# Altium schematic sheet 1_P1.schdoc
size 431 x 309 mm; Symbol: Sheet-Symbol_A4; Device: Sheet-Symbol_A4; @Page Name: P1; @Create Date: 2023-06-03; @Page Count: 1; @Page No: 1; @Project Name: ESP32-S3最小系统板; @Schematic Name: Schematic1; @Update Date: 2023-06-13; Company: 嘉立创EDA; Page Size: A4; Version: V1.0
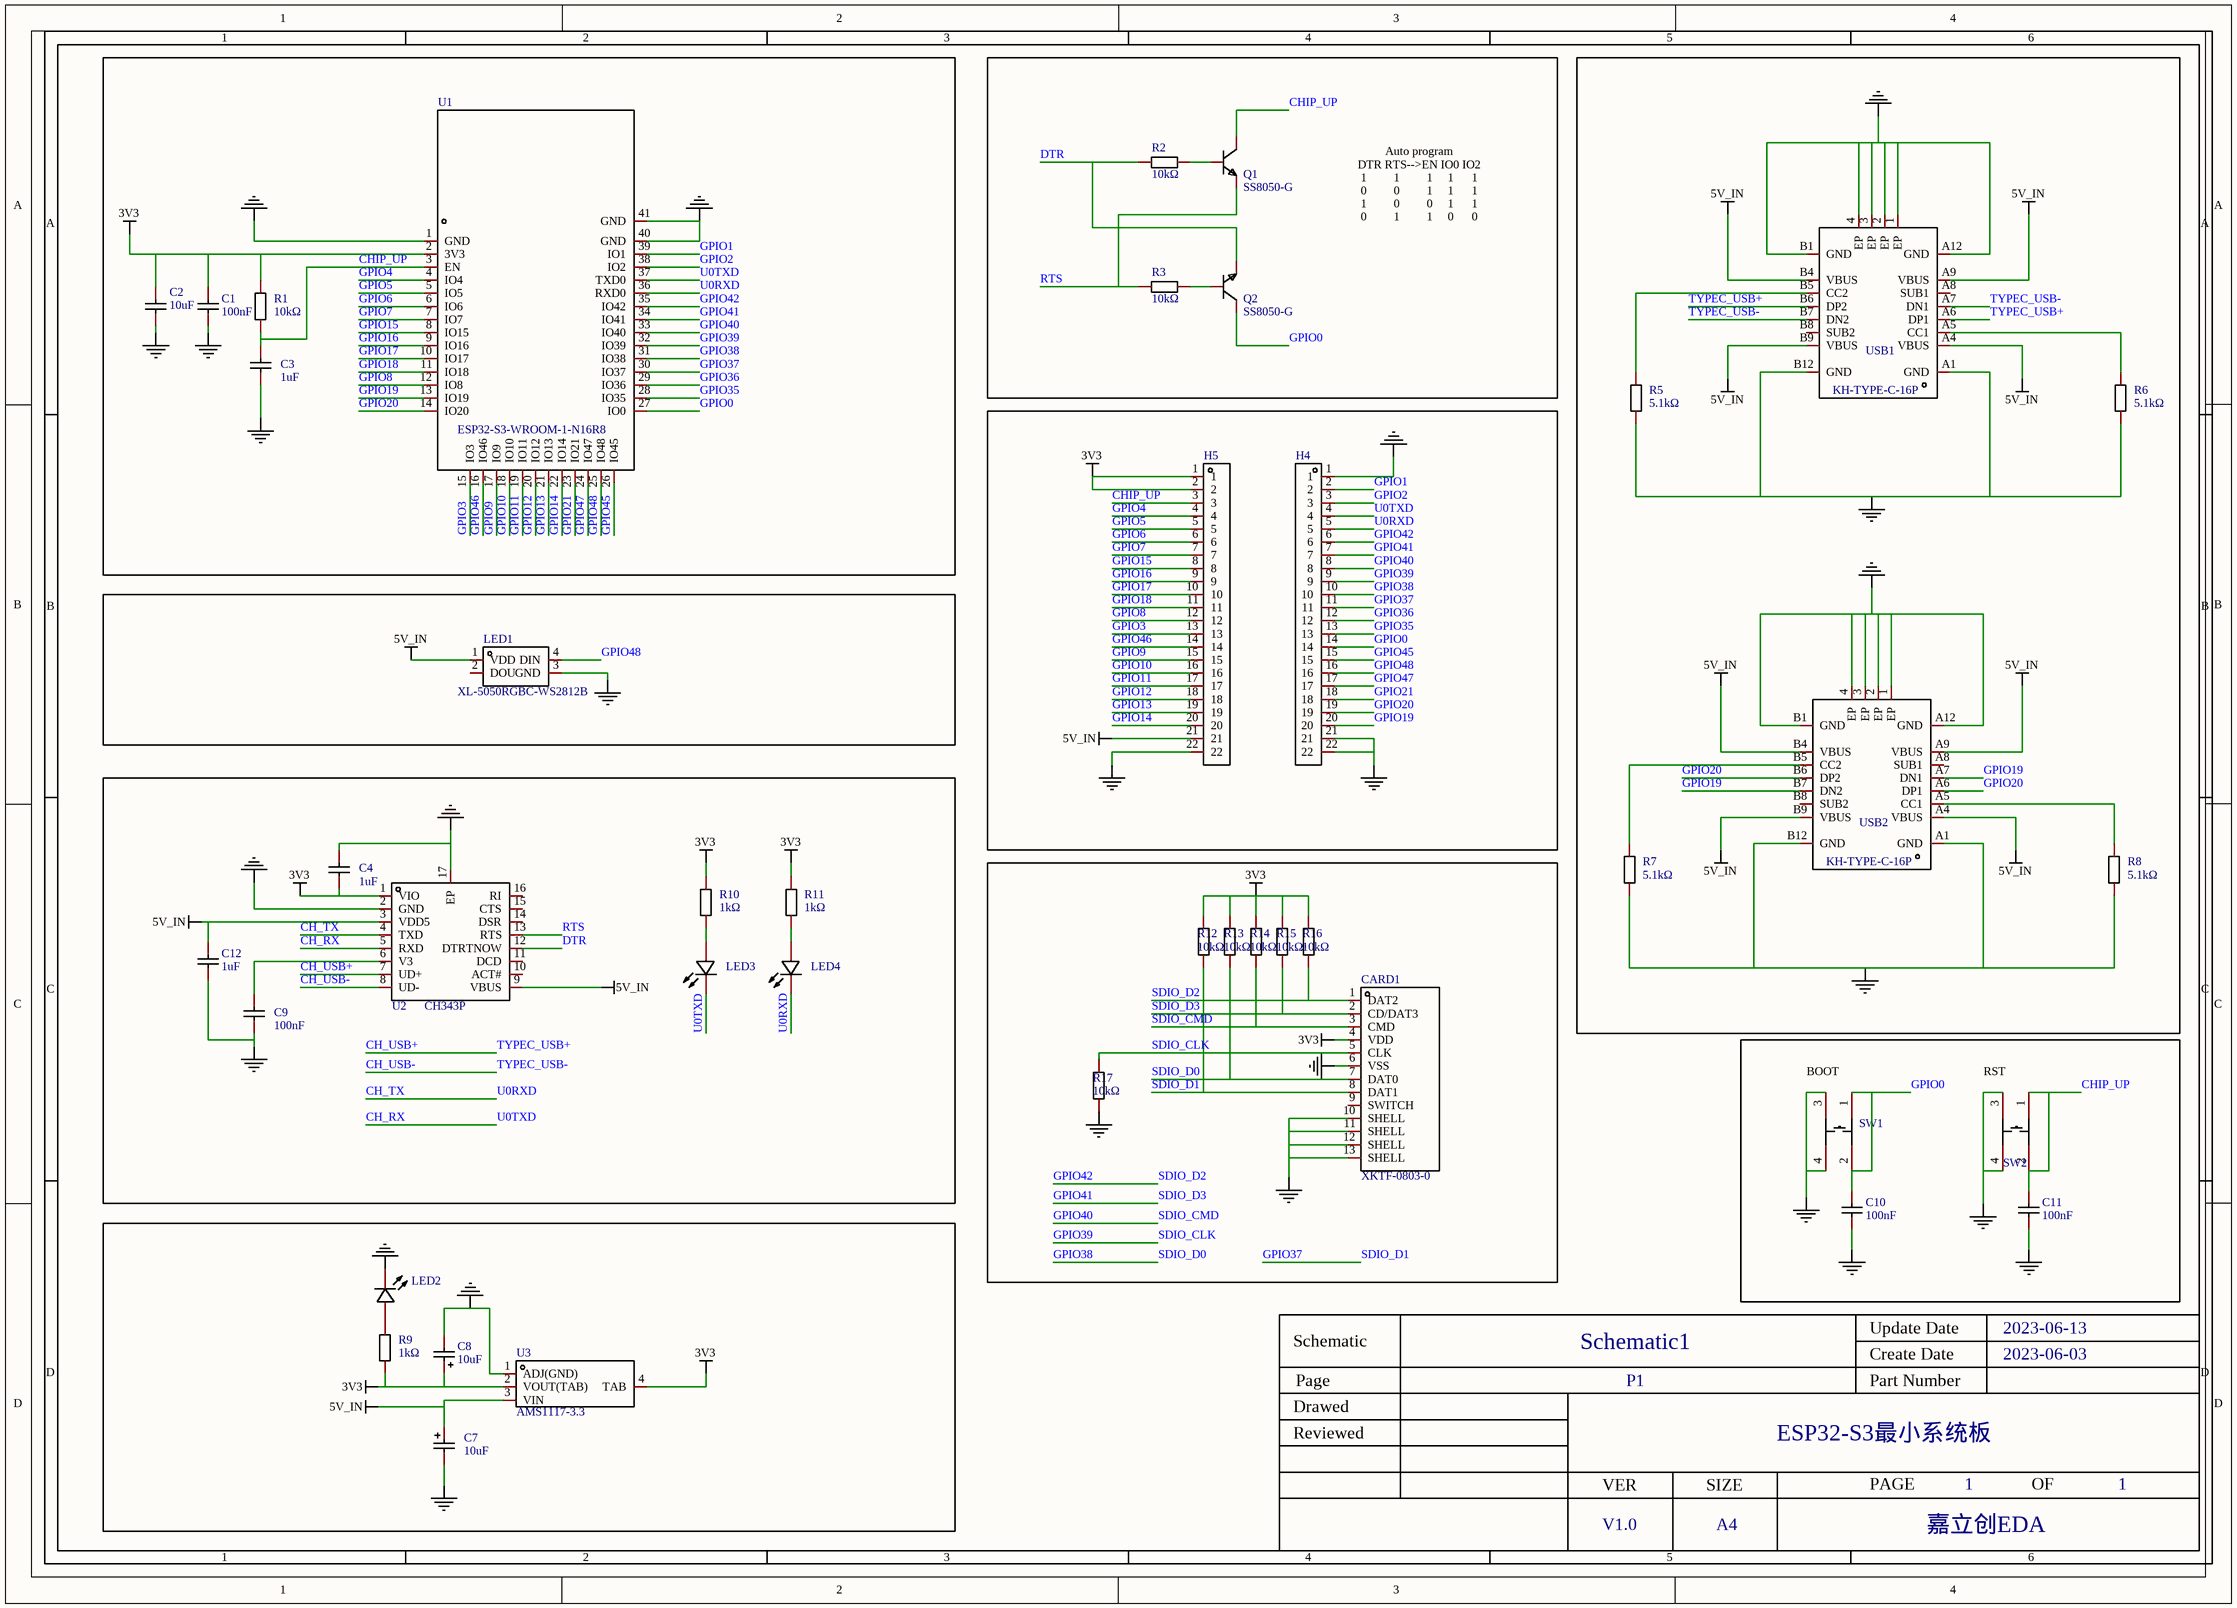
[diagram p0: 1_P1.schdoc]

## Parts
C1  100nF  [C0805]
C2  10uF  [C0805]
C3  1uF  [C0805]
C4  1uF  [C0805]
C7  10uF  [CAP-SMD_L3.2-W1.6-RD-C7171]
C8  10uF  [CAP-SMD_L3.2-W1.6-RD-C7171]
C9  100nF  [C0805]
C10  100nF  [C0805]
C11  100nF  [C0805]
C12  1uF  [C0805]
CARD1  XKTF-0803-0  [TF-SMD_XKTF-0803-0]
H4  X6511WV-22H-C30D60  [HDR-TH_22P-P2.54-V-M]  (value not drawn)
H5  X6511WV-22H-C30D60  [HDR-TH_22P-P2.54-V-M]  (value not drawn)
LED1  XL-5050RGBC-WS2812B  [LED-SMD_4P-L5.0-W5.0-BL_XL-5050RGBC]
LED2  NCD0805R1  [LED0805-RD_RED]  (value not drawn)
LED3  SZYY0805B  [LED0805-R-RD_BLUE]  (value not drawn)
LED4  SZYY0805B  [LED0805-R-RD_BLUE]  (value not drawn)
Q1  SS8050-G  [SOT-23-3_L2.9-W1.6-P1.90-LS2.8-BR]
Q2  SS8050-G  [SOT-23-3_L2.9-W1.6-P1.90-LS2.8-BR]
R1  10kΩ  [R0805]
R2  10kΩ  [R0805]
R3  10kΩ  [R0805]
R5  5.1kΩ  [R0805]
R6  5.1kΩ  [R0805]
R7  5.1kΩ  [R0805]
R8  5.1kΩ  [R0805]
R9  1kΩ  [R0805]
R10  1kΩ  [R0805]
R11  1kΩ  [R0805]
R12  10kΩ  [R0805]
R13  10kΩ  [R0805]
R14  10kΩ  [R0805]
R15  10kΩ  [R0805]
R16  10kΩ  [R0805]
R17  10kΩ  [R0805]
SW1  SKRPACE010  [KEY-SMD_4P-L4.2-W3.2-P2.20-LS4.6]  (value not drawn)
SW2  SKRPACE010  [KEY-SMD_4P-L4.2-W3.2-P2.20-LS4.6]  (value not drawn)
U1  ESP32-S3-WROOM-1-N16R8  [WIRELM-SMD_ESP32-S3-WROOM-1]
U2  CH343P  [TQFN-16_L3.0-W3.0-P0.50-BL-EP1.7]
U3  AMS1117-3.3  [SOT-223-4_L6.5-W3.5-P2.30-LS7.0-BR]
USB1  KH-TYPE-C-16P  [USB-C-SMD_KH-TYPE-C-16P]
USB2  KH-TYPE-C-16P  [USB-C-SMD_KH-TYPE-C-16P]

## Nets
3V3: C1.2 C2.2 C4.1 C8.1 CARD1.4(VDD) H5.1 H5.2 R1.2 R9.1 R10.2 R11.2 R12.2 R13.2 R14.2 R15.2 R16.2 U1.2(3V3) U2.1(VIO) U3.2(VOUT(TAB)) U3.4(TAB)
5V_IN: C7.1 C12.2 H5.21 LED1.1(VDD) U2.3(VDD5) U2.9(VBUS) U3.3(VIN) USB1.A4(VBUS) USB1.A9(VBUS) USB1.B4(VBUS) USB1.B9(VBUS) USB2.A4(VBUS) USB2.A9(VBUS) USB2.B4(VBUS) USB2.B9(VBUS)
NetC1_1: C1.1 C2.1 C3.1 C4.2 C7.2 C8.2 C9.1 C10.1 C11.1 C12.1 CARD1.6(VSS) CARD1.10(SHELL) CARD1.11(SHELL) CARD1.12(SHELL) CARD1.13(SHELL) H4.1 H4.21 H4.22 H5.22 LED1.3(GND) LED2.1(-) R5.1 R6.1 R7.1 R8.1 R17.1 SW1.3 SW1.4 SW2.3 SW2.4 U1.1(GND) U1.40(GND) U1.41(GND) U2.2(GND) U2.17(EP) U3.1(ADJ(GND)) USB1.1(EP) USB1.2(EP) USB1.3(EP) USB1.4(EP) USB1.A1(GND) USB1.A12(GND) USB1.B1(GND) USB1.B12(GND) USB2.1(EP) USB2.2(EP) USB2.3(EP) USB2.4(EP) USB2.A1(GND) USB2.A12(GND) USB2.B1(GND) USB2.B12(GND)
CH_RX: H4.4 LED3.2(-) U1.37(TXD0) U2.5(RXD)  [also labelled U0TXD]
CH_TX: H4.5 LED4.2(-) U1.36(RXD0) U2.4(TXD)  [also labelled U0RXD]
CH_USB+: U2.7(UD+) USB1.A6(DP1) USB1.B6(DP2)  [also labelled TYPEC_USB+]
CH_USB-: U2.8(UD-) USB1.A7(DN1) USB1.B7(DN2)  [also labelled TYPEC_USB-]
CHIP_UP: C3.2 C11.2 H5.3 Q1.3(C) R1.1 SW2.1 SW2.2 U1.3(EN)
DTR: Q2.2(E) R2.2 U2.12(DTRTNOW)
GPIO0: C10.2 H4.14 Q2.3(C) SW1.1 SW1.2 U1.27(IO0)
GPIO1: H4.2 U1.39(IO1)
GPIO2: H4.3 U1.38(IO2)
GPIO3: H5.13 U1.15(IO3)
GPIO4: H5.4 U1.4(IO4)
GPIO5: H5.5 U1.5(IO5)
GPIO6: H5.6 U1.6(IO6)
GPIO7: H5.7 U1.7(IO7)
GPIO8: H5.12 U1.12(IO8)
GPIO9: H5.15 U1.17(IO9)
GPIO10: H5.16 U1.18(IO10)
GPIO11: H5.17 U1.19(IO11)
GPIO12: H5.18 U1.20(IO12)
GPIO13: H5.19 U1.21(IO13)
GPIO14: H5.20 U1.22(IO14)
GPIO15: H5.8 U1.8(IO15)
GPIO16: H5.9 U1.9(IO16)
GPIO17: H5.10 U1.10(IO17)
GPIO18: H5.11 U1.11(IO18)
GPIO19: H4.20 U1.13(IO19) USB2.A7(DN1) USB2.B7(DN2)
GPIO20: H4.19 U1.14(IO20) USB2.A6(DP1) USB2.B6(DP2)
GPIO21: H4.18 U1.23(IO21)
GPIO35: H4.13 U1.28(IO35)
GPIO36: H4.12 U1.29(IO36)
GPIO37: CARD1.8(DAT1) H4.11 R12.1 U1.30(IO37)  [also labelled SDIO_D1]
GPIO38: CARD1.7(DAT0) H4.10 R13.1 U1.31(IO38)  [also labelled SDIO_D0]
GPIO39: CARD1.5(CLK) H4.9 R17.2 U1.32(IO39)  [also labelled SDIO_CLK]
GPIO40: CARD1.3(CMD) H4.8 R14.1 U1.33(IO40)  [also labelled SDIO_CMD]
GPIO41: CARD1.2(CD/DAT3) H4.7 R15.1 U1.34(IO41)  [also labelled SDIO_D3]
GPIO42: CARD1.1(DAT2) H4.6 R16.1 U1.35(IO42)  [also labelled SDIO_D2]
GPIO45: H4.15 U1.26(IO45)
GPIO46: H5.14 U1.16(IO46)
GPIO47: H4.17 U1.24(IO47)
GPIO48: H4.16 LED1.4(DIN) U1.25(IO48)
RTS: Q1.2(E) R3.2 U2.13(RTS)
NetC9_2: C9.2 U2.6(V3)
NetLED2_2: LED2.2(+) R9.2
NetLED3_1: LED3.1(+) R10.1
NetLED4_1: LED4.1(+) R11.1
NetQ1_1: Q1.1(B) R2.1
NetQ2_1: Q2.1(B) R3.1
NetR5_2: R5.2 USB1.B5(CC2)
NetR6_2: R6.2 USB1.A5(CC1)
NetR7_2: R7.2 USB2.B5(CC2)
NetR8_2: R8.2 USB2.A5(CC1)

Not connected (* = marked no-connect by the designer): CARD1 9(SWITCH); LED1 2(DOU); U2 10(ACT#) 11(DCD) 14(DSR) 15(CTS) 16(RI); USB1 A8(SUB1) B8(SUB2); USB2 A8(SUB1) B8(SUB2)

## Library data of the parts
C1 C9-C11 = 0805B104K500NT: 容值:100nF;精度:±10%;额定电压:50V;材质(温度系数):X7R;; Manufacturer: FH(风华); Add into BOM: yes; Tolerance: ±10%; Voltage Rated: 50V; Temperature Coefficient: X7R
C2 = CL21A106KOQNNNE: 容值:10uF;精度:±10%;额定电压:16V;材质(温度系数):X5R;; Manufacturer: SAMSUNG(三星); Add into BOM: yes; Tolerance: ±10%; Voltage Rated: 16V; Temperature Coefficient: X5R
C3 C4 C12 = CL21B105KBFNNNE: 容值:1uF;精度:±10%;额定电压:50V;材质(温度系数):X7R;; Manufacturer: SAMSUNG(三星); Add into BOM: yes; Tolerance: ±10%; Voltage Rated: 50V; Temperature Coefficient: X7R
C7 C8 = TAJA106K016RNJ: 容值:10uF;精度:±10%;额定电压:16V;等效串联电阻:3Ω@100kHz;; Manufacturer: Kyocera AVX; Add into BOM: yes; Tolerance: ±10%; Rated Voltage: 16V
CARD1 = XKTF-0803-0: 卡连接方式:拔插式;卡类型:MicroSD卡(TF卡);连接器类型:卡座;本体最大高度:1.5mm;触头材质:铜合金;触头镀层:金;工作温度范围:-25℃~+80℃;焊接温度(最大值):260℃;; Manufacturer: XKB Connectivity(中国星坤); Add into BOM: yes; Card Connection Mode: 拔插式; Connector Type: 卡座; Maximum Body Height: 1.5mm; Welding Temperature (Max): 260℃
H4 H5 = X6511WV-22H-C30D60: 排数:单排;总PIN位数:22;间距:2.54mm;插针结构:1x22P;行距:-;安装类型:直插;圆针/方针:方针;额定电流:3A;额定电压:250V;配合针长度:6mm;塑高:2.5mm;端接针长度:3mm;触头材质:黄铜;触头镀层:金;工作温度范围:-40℃~+105℃;焊接温度(最大值):260℃;颜色:黑色;; Manufacturer: XKB Connectivity(中国星坤); Add into BOM: yes; Pitch: 2.54mm; Pin Structure: 1x22P; Circluar Pins/Square Pins: 方针; Current Rating (Max): 3A; Voltage Rating (Max): 250V; Welding Temperature (Max): 260℃
LED1 = XL-5050RGBC-WS2812B: 发光颜色:RGB三色;二极管配置:-;主波长:-;色温:-;功率:-;安装方式:正贴;; Manufacturer: XINGLIGHT(成兴光); Add into BOM: yes; Emitted Color: RGB三色; Lens Color: 无色透明; Peak Wavelength: 625nm；470nm；530nm; Viewing Angle: 120°; Mounting Sytle: 正贴
LED2 = NCD0805R1: 发光颜色:红灯;; Manufacturer: 国星光电; Symbol: FC-2012HRK-620D; Add into BOM: yes; Emitted Color: 红灯
LED3 LED4 = SZYY0805B: 发光颜色:蓝灯;二极管配置:-;主波长:460nm~475nm;色温:-;功率:100mW;安装方式:-;; Manufacturer: yongyu(永裕光电); Add into BOM: yes; Emitted Color: 蓝灯; Lens Color: 无色透明; Peak Wavelength: 469nm; Forward Current: 5mA; Power Dissipation: 100mW; Viewing Angle: 120°
Q1 Q2 = SS8050-G_C164886: 晶体管类型:NPN;集射极击穿电压(Vceo):25V;集电极电流(Ic):1.5A;功率(Pd):300mW;直流电流增益(hFE@Ic,Vce):120@100mA,1V;; Manufacturer: CJ(江苏长电/长晶); Add into BOM: yes; Transistor Type: NPN; Collector-Emitter Breakdown Voltage (Vceo): 25V; Collector Current (Ic): 1.5A; Power Dissipation (Pd): 300mW; Collector Cut-Off Current (Icbo): 100nA; Collector-Emitter Saturation Voltage (VCE(sat)@Ic,Ib): 500mV@800mA,80mA; Transition Frequency (fT): 100MHz
R1-R3 R12-R17 = 0805W8F1002T5E_C17414: 电阻类型:厚膜电阻;阻值:10kΩ;精度:±1%;功率:125mW;; Manufacturer: UNI-ROYAL(厚声); Add into BOM: yes; Tolerance: ±1%; Power(Watts): 125mW; Temperature Coefficient: ±100ppm/℃; Overload Voltage (Max): 150V
R5-R8 = 0805W8F5101T5E: 电阻类型:厚膜电阻;阻值:5.1kΩ;精度:±1%;功率:125mW;; Manufacturer: UNI-ROYAL(厚声); Add into BOM: yes; Tolerance: ±1%; Power(Watts): 125mW; Temperature Coefficient: ±100ppm/℃; Overload Voltage (Max): 150V
R9-R11 = RC0805FR-071KL: 电阻类型:厚膜电阻;阻值:1kΩ;精度:±1%;功率:125mW;; Manufacturer: YAGEO(国巨); Add into BOM: yes; Tolerance: ±1%; Power(Watts): 125mW; Temperature Coefficient: ±100ppm/℃; Overload Voltage (Max): 150V
SW1 SW2 = SKRPACE010: 触点电流:50mA;额定电压(DC):16V;电路结构:单刀单掷;安装方式:立贴;带灯:-;机械寿命:-;; Manufacturer: ALPSALPINE(阿尔卑斯阿尔派); Add into BOM: yes; Contact Current: 50mA; Voltage Rating (DC): 16V; Circuit: 单刀单掷; Actuator Style: 椭圆形按钮; Switch Length: 4.2mm; Switch Width: 3.2mm; Switch Height: 2.5mm
U1 = ESP32-S3-WROOM-1-N16R8: Manufacturer: ESPRESSIF(乐鑫); Symbol: ESP32-S3-WROOM-1(N16R8); Add into BOM: yes
U2 = CH343P: 类型:-;协议类别:-;驱动器/接收器数:-;数据速率:-;; Manufacturer: WCH(南京沁恒); Add into BOM: yes
U3 = AMS1117-3.3_C347222: 输出类型:固定;输出极性:正;最大输入电压:18V;输出电压:3.3V;输出电流:1A;电源纹波抑制比(PSRR):60dB@(120Hz);; Manufacturer: UMW(广东友台半导体); Add into BOM: yes; Output Type: 固定; Output Polarity: 正; Number of Outputs: 1; Maximum Input Voltage: 18V; Output Voltage: 3.3V; Dropout Voltage: 1.3V@(1A); Output Current: 1A
USB1 USB2 = KH-TYPE-C-16P: 连接器类型:Type-C;标准:-;公母:母座;触点数量:16;端口数量:1;安装方式:卧贴;额定电流 - 电源:3A;工作温度范围:-40℃~+85℃;; Manufacturer: kinghelm(金航标); Add into BOM: yes; Connector Type: Type-C; Gender: 母座; Number of Contacts: 16; Number of Ports: 1; Current Rating - Power (Max): 3A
